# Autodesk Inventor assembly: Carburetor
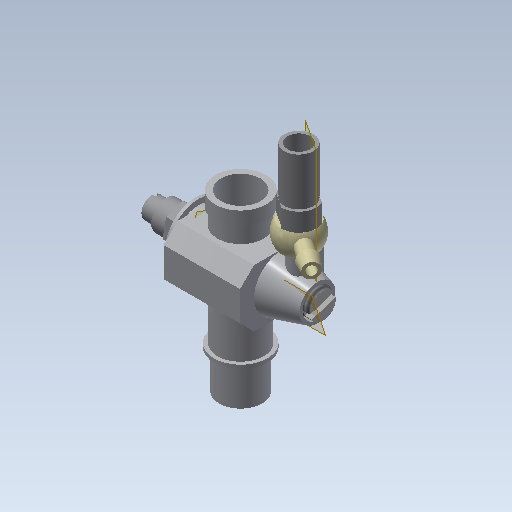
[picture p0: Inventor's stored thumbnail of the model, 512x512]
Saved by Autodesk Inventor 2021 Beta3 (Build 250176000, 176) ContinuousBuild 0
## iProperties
Created: 2012-08
Part Number: Carburetor
Document SubType Name: Assembly
Designer: John
Author: John
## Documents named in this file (8)
- C:\Users\John Helfen\Desktop\Ex_Files_Autodesk_Inventor_2020_EssT\Ex_Files_Autodesk_Inventor_2021_EssT\Exercise Files\01_Basic concepts\01_03\Carburetor.iam
- C:\Users\John Helfen\Desktop\Ex_Files_Autodesk_Inventor_2020_EssT\Ex_Files_Autodesk_Inventor_2021_EssT\Exercise Files\01_Basic concepts\01_03\Gas Regulator.ipt
- C:\Users\John Helfen\Desktop\Ex_Files_Autodesk_Inventor_2020_EssT\Ex_Files_Autodesk_Inventor_2021_EssT\Exercise Files\01_Basic concepts\01_03\Mixture Control.ipt
- C:\Users\John Helfen\Desktop\Ex_Files_Autodesk_Inventor_2020_EssT\Ex_Files_Autodesk_Inventor_2021_EssT\Exercise Files\01_Basic concepts\01_03\Air Adjuster.ipt
- C:\Users\John Helfen\Desktop\Ex_Files_Autodesk_Inventor_2020_EssT\Ex_Files_Autodesk_Inventor_2021_EssT\Exercise Files\01_Basic concepts\01_03\Hex Cap.ipt
- C:\Users\John Helfen\Desktop\Ex_Files_Autodesk_Inventor_2020_EssT\Ex_Files_Autodesk_Inventor_2021_EssT\Exercise Files\01_Basic concepts\01_03\Fuel Intake.ipt
- C:\Users\John Helfen\Desktop\Ex_Files_Autodesk_Inventor_2020_EssT\Ex_Files_Autodesk_Inventor_2021_EssT\Exercise Files\01_Basic concepts\01_03\Fuel Adjuster.ipt
- C:\Users\John Helfen\Desktop\Ex_Files_Autodesk_Inventor_2020_EssT\Ex_Files_Autodesk_Inventor_2021_EssT\Exercise Files\01_Basic concepts\01_03\Carburetor Housing_v3.ipt
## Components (7 placed, 7 different names)
1. Carburetor Housing_v3:2 — Mate:6, Mate:7, Mate:10, Flush:1, Flush:2
2. Gas Regulator:1 — Mate:6, Flush:1
3. Mixture Control:1 — Flush:2
4. Air Adjuster:1
5. Hex Cap:1
6. Fuel Intake:1 — Mate:8, Mate:9, Mate:10
7. Fuel Adjuster:1 — Mate:7, Mate:8, Mate:9
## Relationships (7: Mate 5, Flush 2)
- Mate:6: Carburetor Housing_v3:2 ↔ Gas Regulator:1
- Mate:7: Carburetor Housing_v3:2 ↔ Fuel Adjuster:1
- Mate:8: Fuel Intake:1 ↔ Fuel Adjuster:1
- Mate:9: Fuel Intake:1 ↔ Fuel Adjuster:1
- Mate:10: Carburetor Housing_v3:2 ↔ Fuel Intake:1
- Flush:1: Carburetor Housing_v3:2 ↔ Gas Regulator:1
- Flush:2: Carburetor Housing_v3:2 ↔ Mixture Control:1
